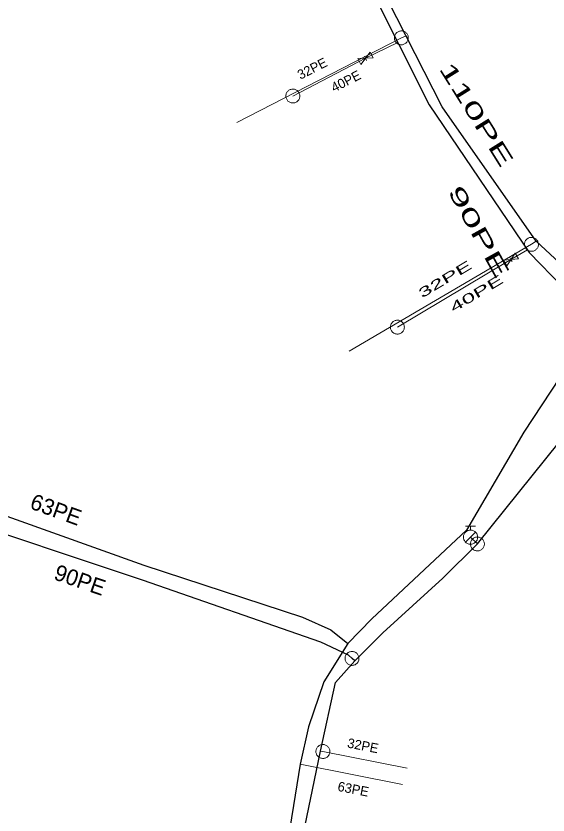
# Model space of a CAD drawing. Extents: x -741806 to -738704, y -1059275 to -1055387.
# Drawn here: x -740322.4 to -740289, y -1057228.9 to -1057178.6 of the extents above; entities that cross this region are included whole.
import ezdxf

# ---------------------------------------------------------------- set-up
doc = ezdxf.new("R2010")
doc.units = 0
doc.header["$LTSCALE"] = 0.4
for name, color, linetype, lineweight in [('2', 7, 'Continuous', 25), ('21', 7, 'Continuous', 13), ('37', 7, 'Continuous', 13), ('46', 7, 'Continuous', 13), ('50', 7, 'Continuous', 13), ('51', 7, 'Continuous', 13), ('52', 7, 'Continuous', 25), ('56', 7, 'Continuous', 13)]:
    doc.layers.add(name, color=color, linetype=linetype, lineweight=lineweight)
for name, color, linetype in [('5', 7, 'Continuous'), ('53', 7, 'Continuous'), ('54', 7, 'Continuous'), ('55', 7, 'Continuous')]:
    doc.layers.add(name, color=color, linetype=linetype)

msp = doc.modelspace()

# ---------------------------------------------------------------- linework, layer by layer
at = {"layer": '2'}
for points in [[(-740262.96, -1057069.909), (-740269.19, -1057072.669), (-740274.949, -1057077.7), (-740275.559, -1057078.32), (-740280.173, -1057082.526), (-740281.937, -1057084.151), (-740283.887, -1057086.098), (-740285.828, -1057088.145), (-740287.55, -1057089.96), (-740294.199, -1057098.5), (-740299.28, -1057106.06), (-740302.629, -1057112.73), (-740305.219, -1057120.72), (-740306.46, -1057125.389), (-740308.809, -1057139.85), (-740308.96, -1057146.77), (-740308.55, -1057154.01), (-740307.079, -1057159.62), (-740305.57, -1057163.75), (-740300.92, -1057174.76), (-740300.27, -1057176.629), (-740296.46, -1057184.19), (-740290.177, -1057193.486), (-740285.949, -1057197.84)], [(-740285.949, -1057197.84), (-740290.513, -1057204.772), (-740294.12, -1057210.94), (-740300.07, -1057216.52), (-740301.579, -1057218.07), (-740303.1, -1057220.48), (-740304.059, -1057223.3), (-740304.57, -1057225.659), (-740305.55, -1057231.639), (-740307.182, -1057240.935), (-740308.309, -1057246.08), (-740308.647, -1057246.469)], [(-740351.149, -1057201.84), (-740350.76, -1057202.01), (-740350.539, -1057202.1), (-740336.309, -1057206.55), (-740331.34, -1057207.659), (-740329.829, -1057207.85), (-740325.609, -1057209.139), (-740314.399, -1057213.149), (-740304.43, -1057216.419), (-740302.66, -1057217.22), (-740301.579, -1057218.07)]]:
    msp.add_lwpolyline(points, dxfattribs=at)
at = {"layer": '21'}
for points in [[(-740297.92, -1057179.867), (-740298.219, -1057179.99), (-740308.548, -1057185.308)], [(-740289.74, -1057192.772), (-740290.039, -1057192.97), (-740301.491, -1057199.698)], [(-740303.309, -1057224.83), (-740303.149, -1057224.86), (-740297.85, -1057225.899)]]:
    msp.add_lwpolyline(points, dxfattribs=at)
at = {"layer": '37'}
for p, q in [((-740300.468, -1057181.27), (-740300.538, -1057181.137)), ((-740300.468, -1057181.27), (-740300.399, -1057181.403)), ((-740291.328, -1057193.929), (-740291.405, -1057193.8)), ((-740291.328, -1057193.929), (-740291.252, -1057194.058))]:
    msp.add_line(p, q, dxfattribs=at)
for points in [[(-740300.758, -1057181.654), (-740300.179, -1057180.886), (-740299.988, -1057181.253), (-740300.949, -1057181.287)], [(-740291.595, -1057194.329), (-740291.061, -1057193.529), (-740290.849, -1057193.885), (-740291.807, -1057193.973)]]:
    msp.add_lwpolyline(points, close=True, dxfattribs=at)
at = {"layer": '46'}
for points in [[(-740304.65, -1057183.446), (-740304.674, -1057183.407), (-740304.701, -1057183.371), (-740304.732, -1057183.336), (-740304.766, -1057183.306), (-740304.803, -1057183.28), (-740304.843, -1057183.257), (-740304.885, -1057183.239), (-740304.929, -1057183.224), (-740304.974, -1057183.216), (-740305.019, -1057183.212), (-740305.065, -1057183.212), (-740305.111, -1057183.217), (-740305.155, -1057183.227), (-740305.199, -1057183.241), (-740305.241, -1057183.26), (-740305.28, -1057183.283), (-740305.317, -1057183.311), (-740305.351, -1057183.341), (-740305.381, -1057183.376), (-740305.408, -1057183.414), (-740305.43, -1057183.454), (-740305.448, -1057183.495), (-740305.462, -1057183.539), (-740305.471, -1057183.584), (-740305.476, -1057183.63), (-740305.474, -1057183.675), (-740305.47, -1057183.72), (-740305.46, -1057183.766), (-740305.445, -1057183.809), (-740305.426, -1057183.851), (-740305.403, -1057183.89), (-740305.376, -1057183.926), (-740305.345, -1057183.961), (-740305.31, -1057183.991), (-740305.274, -1057184.017), (-740305.234, -1057184.04), (-740305.192, -1057184.058), (-740305.147, -1057184.072), (-740305.103, -1057184.081), (-740305.058, -1057184.085), (-740305.012, -1057184.085), (-740304.966, -1057184.08), (-740304.921, -1057184.071), (-740304.878, -1057184.056), (-740304.836, -1057184.037), (-740304.797, -1057184.014), (-740304.76, -1057183.987), (-740304.726, -1057183.956), (-740304.696, -1057183.921), (-740304.669, -1057183.883), (-740304.647, -1057183.843), (-740304.628, -1057183.802), (-740304.615, -1057183.758), (-740304.606, -1057183.713), (-740304.601, -1057183.667), (-740304.602, -1057183.621), (-740304.607, -1057183.577), (-740304.617, -1057183.531), (-740304.632, -1057183.488), (-740304.65, -1057183.447)], [(-740298.092, -1057197.954), (-740298.118, -1057197.917), (-740298.147, -1057197.882), (-740298.18, -1057197.849), (-740298.216, -1057197.821), (-740298.255, -1057197.797), (-740298.296, -1057197.776), (-740298.339, -1057197.761), (-740298.383, -1057197.749), (-740298.428, -1057197.743), (-740298.474, -1057197.741), (-740298.52, -1057197.744), (-740298.566, -1057197.752), (-740298.609, -1057197.765), (-740298.652, -1057197.781), (-740298.692, -1057197.803), (-740298.731, -1057197.828), (-740298.765, -1057197.858), (-740298.798, -1057197.89), (-740298.826, -1057197.926), (-740298.85, -1057197.965), (-740298.87, -1057198.006), (-740298.886, -1057198.048), (-740298.897, -1057198.093), (-740298.904, -1057198.138), (-740298.906, -1057198.185), (-740298.902, -1057198.23), (-740298.895, -1057198.275), (-740298.883, -1057198.32), (-740298.866, -1057198.362), (-740298.844, -1057198.402), (-740298.819, -1057198.44), (-740298.79, -1057198.475), (-740298.757, -1057198.508), (-740298.72, -1057198.536), (-740298.682, -1057198.56), (-740298.641, -1057198.581), (-740298.598, -1057198.596), (-740298.553, -1057198.608), (-740298.509, -1057198.614), (-740298.463, -1057198.616), (-740298.417, -1057198.613), (-740298.371, -1057198.605), (-740298.328, -1057198.593), (-740298.285, -1057198.576), (-740298.245, -1057198.554), (-740298.206, -1057198.529), (-740298.171, -1057198.5), (-740298.139, -1057198.467), (-740298.111, -1057198.431), (-740298.087, -1057198.392), (-740298.067, -1057198.351), (-740298.05, -1057198.308), (-740298.04, -1057198.264), (-740298.033, -1057198.219), (-740298.031, -1057198.172), (-740298.034, -1057198.126), (-740298.042, -1057198.082), (-740298.054, -1057198.037), (-740298.071, -1057197.995), (-740298.092, -1057197.955)]]:
    msp.add_lwpolyline(points, dxfattribs=at)
at = {"layer": '50'}
for p, q in [((-740294.178, -1057210.685), (-740293.87, -1057210.685)), ((-740293.87, -1057210.936), (-740293.87, -1057210.685)), ((-740293.563, -1057210.685), (-740293.87, -1057210.685)), ((-740293.87, -1057211.383), (-740294.187, -1057211.7)), ((-740293.87, -1057211.383), (-740293.554, -1057211.071))]:
    msp.add_line(p, q, dxfattribs=at)
msp.add_lwpolyline([(-740293.426, -1057211.387), (-740293.428, -1057211.338), (-740293.433, -1057211.292), (-740293.446, -1057211.246), (-740293.463, -1057211.203), (-740293.482, -1057211.163), (-740293.509, -1057211.122), (-740293.538, -1057211.087), (-740293.571, -1057211.052), (-740293.606, -1057211.022), (-740293.646, -1057210.998), (-740293.687, -1057210.976), (-740293.73, -1057210.957), (-740293.776, -1057210.947), (-740293.822, -1057210.939), (-740293.868, -1057210.936), (-740293.914, -1057210.939), (-740293.959, -1057210.944), (-740294.005, -1057210.957), (-740294.049, -1057210.974), (-740294.092, -1057210.995), (-740294.13, -1057211.02), (-740294.167, -1057211.049), (-740294.2, -1057211.082), (-740294.229, -1057211.117), (-740294.256, -1057211.157), (-740294.278, -1057211.198), (-740294.294, -1057211.241), (-740294.308, -1057211.287), (-740294.313, -1057211.333), (-740294.32, -1057211.379), (-740294.317, -1057211.427), (-740294.309, -1057211.473), (-740294.298, -1057211.516), (-740294.282, -1057211.562), (-740294.26, -1057211.603), (-740294.236, -1057211.643), (-740294.206, -1057211.678), (-740294.174, -1057211.713), (-740294.136, -1057211.743), (-740294.098, -1057211.767), (-740294.055, -1057211.789), (-740294.012, -1057211.805), (-740293.969, -1057211.819), (-740293.92, -1057211.827), (-740293.874, -1057211.83), (-740293.828, -1057211.827), (-740293.782, -1057211.819), (-740293.736, -1057211.808), (-740293.693, -1057211.792), (-740293.65, -1057211.77), (-740293.612, -1057211.746), (-740293.574, -1057211.716), (-740293.542, -1057211.684), (-740293.512, -1057211.649), (-740293.488, -1057211.608), (-740293.464, -1057211.568), (-740293.447, -1057211.524), (-740293.437, -1057211.479), (-740293.429, -1057211.433)], close=True, dxfattribs=at)
at = {"layer": '51'}
for points in [[(-740298.623, -1057180.155), (-740298.604, -1057180.195), (-740298.581, -1057180.234), (-740298.553, -1057180.272), (-740298.522, -1057180.304), (-740298.487, -1057180.334), (-740298.449, -1057180.361), (-740298.409, -1057180.382), (-740298.367, -1057180.401), (-740298.323, -1057180.413), (-740298.278, -1057180.422), (-740298.232, -1057180.426), (-740298.186, -1057180.425), (-740298.141, -1057180.42), (-740298.097, -1057180.409), (-740298.053, -1057180.393), (-740298.011, -1057180.374), (-740297.972, -1057180.351), (-740297.936, -1057180.323), (-740297.903, -1057180.291), (-740297.873, -1057180.256), (-740297.847, -1057180.218), (-740297.824, -1057180.179), (-740297.807, -1057180.136), (-740297.794, -1057180.093), (-740297.785, -1057180.047), (-740297.781, -1057180.001), (-740297.783, -1057179.956), (-740297.788, -1057179.91), (-740297.799, -1057179.866), (-740297.814, -1057179.822), (-740297.834, -1057179.782), (-740297.857, -1057179.743), (-740297.885, -1057179.706), (-740297.916, -1057179.673), (-740297.951, -1057179.643), (-740297.989, -1057179.616), (-740298.029, -1057179.595), (-740298.071, -1057179.576), (-740298.115, -1057179.564), (-740298.16, -1057179.555), (-740298.205, -1057179.551), (-740298.252, -1057179.552), (-740298.297, -1057179.558), (-740298.341, -1057179.568), (-740298.385, -1057179.584), (-740298.426, -1057179.603), (-740298.465, -1057179.627), (-740298.502, -1057179.654), (-740298.535, -1057179.686), (-740298.565, -1057179.721), (-740298.591, -1057179.759), (-740298.613, -1057179.798), (-740298.63, -1057179.841), (-740298.644, -1057179.884), (-740298.652, -1057179.93), (-740298.656, -1057179.976), (-740298.655, -1057180.021), (-740298.649, -1057180.067), (-740298.639, -1057180.111), (-740298.624, -1057180.154)], [(-740290.403, -1057193.21), (-740290.377, -1057193.246), (-740290.346, -1057193.28), (-740290.312, -1057193.311), (-740290.275, -1057193.337), (-740290.235, -1057193.36), (-740290.193, -1057193.379), (-740290.149, -1057193.392), (-740290.104, -1057193.402), (-740290.059, -1057193.405), (-740290.013, -1057193.405), (-740289.968, -1057193.4), (-740289.922, -1057193.391), (-740289.879, -1057193.376), (-740289.838, -1057193.357), (-740289.798, -1057193.334), (-740289.761, -1057193.307), (-740289.727, -1057193.276), (-740289.697, -1057193.242), (-740289.67, -1057193.204), (-740289.648, -1057193.164), (-740289.63, -1057193.122), (-740289.615, -1057193.079), (-740289.607, -1057193.034), (-740289.602, -1057192.989), (-740289.602, -1057192.942), (-740289.607, -1057192.896), (-740289.617, -1057192.853), (-740289.632, -1057192.808), (-740289.651, -1057192.767), (-740289.674, -1057192.727), (-740289.701, -1057192.691), (-740289.732, -1057192.657), (-740289.767, -1057192.626), (-740289.803, -1057192.6), (-740289.843, -1057192.578), (-740289.885, -1057192.559), (-740289.929, -1057192.546), (-740289.974, -1057192.536), (-740290.019, -1057192.532), (-740290.065, -1057192.532), (-740290.111, -1057192.537), (-740290.156, -1057192.547), (-740290.199, -1057192.562), (-740290.241, -1057192.58), (-740290.28, -1057192.604), (-740290.317, -1057192.631), (-740290.351, -1057192.662), (-740290.381, -1057192.695), (-740290.408, -1057192.733), (-740290.43, -1057192.773), (-740290.448, -1057192.815), (-740290.463, -1057192.858), (-740290.471, -1057192.904), (-740290.476, -1057192.949), (-740290.476, -1057192.995), (-740290.471, -1057193.041), (-740290.461, -1057193.085), (-740290.446, -1057193.129), (-740290.427, -1057193.17), (-740290.404, -1057193.209)], [(-740293.128, -1057211.503), (-740293.161, -1057211.472), (-740293.198, -1057211.445), (-740293.238, -1057211.422), (-740293.279, -1057211.403), (-740293.322, -1057211.389), (-740293.368, -1057211.378), (-740293.413, -1057211.374), (-740293.459, -1057211.373), (-740293.504, -1057211.378), (-740293.549, -1057211.387), (-740293.593, -1057211.401), (-740293.635, -1057211.419), (-740293.675, -1057211.441), (-740293.712, -1057211.468), (-740293.746, -1057211.499), (-740293.777, -1057211.532), (-740293.804, -1057211.569), (-740293.827, -1057211.608), (-740293.846, -1057211.651), (-740293.861, -1057211.695), (-740293.87, -1057211.739), (-740293.876, -1057211.784), (-740293.876, -1057211.83), (-740293.872, -1057211.875), (-740293.862, -1057211.921), (-740293.848, -1057211.965), (-740293.83, -1057212.006), (-740293.807, -1057212.046), (-740293.78, -1057212.083), (-740293.75, -1057212.118), (-740293.717, -1057212.148), (-740293.68, -1057212.175), (-740293.64, -1057212.199), (-740293.599, -1057212.217), (-740293.555, -1057212.232), (-740293.51, -1057212.242), (-740293.465, -1057212.247), (-740293.419, -1057212.248), (-740293.374, -1057212.242), (-740293.329, -1057212.233), (-740293.285, -1057212.22), (-740293.242, -1057212.202), (-740293.203, -1057212.178), (-740293.166, -1057212.153), (-740293.132, -1057212.122), (-740293.1, -1057212.088), (-740293.074, -1057212.051), (-740293.05, -1057212.012), (-740293.032, -1057211.97), (-740293.017, -1057211.926), (-740293.008, -1057211.881), (-740293.002, -1057211.836), (-740293.002, -1057211.79), (-740293.006, -1057211.745), (-740293.016, -1057211.7), (-740293.029, -1057211.656), (-740293.047, -1057211.615), (-740293.071, -1057211.574), (-740293.097, -1057211.537), (-740293.127, -1057211.504)], [(-740301.655, -1057218.729), (-740301.682, -1057218.765), (-740301.706, -1057218.804), (-740301.725, -1057218.847), (-740301.74, -1057218.889), (-740301.75, -1057218.934), (-740301.756, -1057218.98), (-740301.756, -1057219.025), (-740301.752, -1057219.071), (-740301.743, -1057219.116), (-740301.729, -1057219.159), (-740301.711, -1057219.202), (-740301.689, -1057219.242), (-740301.663, -1057219.28), (-740301.633, -1057219.314), (-740301.599, -1057219.345), (-740301.562, -1057219.373), (-740301.523, -1057219.396), (-740301.482, -1057219.415), (-740301.438, -1057219.43), (-740301.393, -1057219.44), (-740301.348, -1057219.445), (-740301.302, -1057219.446), (-740301.256, -1057219.441), (-740301.212, -1057219.433), (-740301.168, -1057219.419), (-740301.125, -1057219.401), (-740301.086, -1057219.379), (-740301.048, -1057219.352), (-740301.014, -1057219.322), (-740300.982, -1057219.289), (-740300.956, -1057219.252), (-740300.932, -1057219.213), (-740300.913, -1057219.171), (-740300.898, -1057219.128), (-740300.888, -1057219.084), (-740300.882, -1057219.038), (-740300.882, -1057218.992), (-740300.885, -1057218.946), (-740300.895, -1057218.902), (-740300.908, -1057218.858), (-740300.926, -1057218.816), (-740300.949, -1057218.775), (-740300.975, -1057218.739), (-740301.005, -1057218.704), (-740301.039, -1057218.673), (-740301.075, -1057218.645), (-740301.115, -1057218.622), (-740301.156, -1057218.602), (-740301.2, -1057218.588), (-740301.245, -1057218.578), (-740301.29, -1057218.573), (-740301.336, -1057218.571), (-740301.381, -1057218.576), (-740301.426, -1057218.584), (-740301.47, -1057218.598), (-740301.513, -1057218.616), (-740301.552, -1057218.638), (-740301.59, -1057218.665), (-740301.624, -1057218.695), (-740301.654, -1057218.729)], [(-740302.719, -1057224.941), (-740302.713, -1057224.896), (-740302.711, -1057224.85), (-740302.715, -1057224.804), (-740302.723, -1057224.76), (-740302.736, -1057224.716), (-740302.753, -1057224.673), (-740302.775, -1057224.633), (-740302.801, -1057224.595), (-740302.831, -1057224.56), (-740302.864, -1057224.529), (-740302.9, -1057224.501), (-740302.939, -1057224.476), (-740302.98, -1057224.456), (-740303.023, -1057224.441), (-740303.068, -1057224.43), (-740303.114, -1057224.424), (-740303.159, -1057224.423), (-740303.205, -1057224.426), (-740303.25, -1057224.435), (-740303.294, -1057224.448), (-740303.336, -1057224.466), (-740303.377, -1057224.487), (-740303.414, -1057224.513), (-740303.449, -1057224.542), (-740303.481, -1057224.576), (-740303.509, -1057224.612), (-740303.533, -1057224.651), (-740303.553, -1057224.693), (-740303.568, -1057224.736), (-740303.579, -1057224.78), (-740303.585, -1057224.825), (-740303.586, -1057224.871), (-740303.583, -1057224.917), (-740303.575, -1057224.961), (-740303.561, -1057225.005), (-740303.544, -1057225.048), (-740303.522, -1057225.088), (-740303.497, -1057225.126), (-740303.466, -1057225.161), (-740303.434, -1057225.192), (-740303.397, -1057225.22), (-740303.358, -1057225.245), (-740303.317, -1057225.264), (-740303.274, -1057225.28), (-740303.229, -1057225.29), (-740303.184, -1057225.297), (-740303.138, -1057225.297), (-740303.093, -1057225.295), (-740303.047, -1057225.286), (-740303.003, -1057225.273), (-740302.961, -1057225.255), (-740302.921, -1057225.234), (-740302.883, -1057225.208), (-740302.848, -1057225.179), (-740302.816, -1057225.145), (-740302.788, -1057225.109), (-740302.765, -1057225.07), (-740302.745, -1057225.028), (-740302.73, -1057224.985), (-740302.719, -1057224.942)]]:
    msp.add_lwpolyline(points, dxfattribs=at)
at = {"layer": '52'}
msp.add_line((-740293.44, -1057211.81), (-740293.87, -1057211.379), dxfattribs=at)
for points in [[(-740283.129, -1057198.97), (-740283.26, -1057198.81), (-740289.74, -1057192.772), (-740295.66, -1057184.32), (-740299.64, -1057176.48), (-740305.079, -1057163.11), (-740306.469, -1057159.919), (-740308.03, -1057153.929), (-740308.37, -1057146.06), (-740307.77, -1057139.98), (-740305.71, -1057125.55), (-740304.82, -1057121.77), (-740302.16, -1057112.889), (-740299.12, -1057106.889), (-740298.43, -1057105.73), (-740293.78, -1057098.919), (-740287, -1057090.56), (-740282.309, -1057085.5), (-740278.449, -1057081.76), (-740275.899, -1057079.48), (-740275.289, -1057078.97), (-740268.949, -1057073.48), (-740263.329, -1057070.639), (-740262.78, -1057070.48)], [(-740317.443, -1057290.145), (-740317.35, -1057289.69), (-740316.219, -1057284.629), (-740312.52, -1057267.659), (-740311.399, -1057262.36), (-740306.51, -1057241.179), (-740304.539, -1057230.81), (-740303.309, -1057224.83), (-740302.359, -1057220.52), (-740301.14, -1057219.159), (-740299.39, -1057217.389), (-740295.62, -1057213.96), (-740293.44, -1057211.81), (-740283.129, -1057198.97)], [(-740301.14, -1057219.159), (-740301.32, -1057219.01), (-740301.539, -1057218.81), (-740303.28, -1057217.99), (-740314.489, -1057214.08), (-740327.18, -1057209.85), (-740330.829, -1057208.86), (-740336.92, -1057207.07), (-740350.059, -1057202.919), (-740350.629, -1057202.74), (-740351.27, -1057202.44)]]:
    msp.add_lwpolyline(points, dxfattribs=at)
at = {"layer": '56'}
msp.add_line((-740298.149, -1057226.94), (-740304.57, -1057225.659), dxfattribs=at)
for points in [[(-740305.039, -1057183.649), (-740300.469, -1057181.27), (-740298.43, -1057180.28)], [(-740298.469, -1057198.179), (-740291.329, -1057193.929), (-740290.295, -1057193.311)]]:
    msp.add_lwpolyline(points, dxfattribs=at)

# ---------------------------------------------------------------- texts
at = {"layer": '5', "width": 1.95}
msp.add_text('90PE', height=1, rotation=299, dxfattribs=at).set_placement((-740295.332, -1057189.627))
at = {"layer": '5'}
msp.add_text('63PE', height=1, rotation=340, dxfattribs=at).set_placement((-740321.63, -1057209.562))
at = {"layer": '53', "width": 1.85}
msp.add_text('110PE ', height=1, rotation=302, dxfattribs=at).set_placement((-740295.887, -1057181.917))
at = {"layer": '53'}
msp.add_text('90PE', height=1, rotation=341, dxfattribs=at).set_placement((-740320.122, -1057214.02))
at = {"layer": '54'}
for rotation, p in [(27, (-740304.56, -1057182.627)), (349, (-740301.652, -1057224.601))]:
    msp.add_text('32PE', height=0.6, rotation=rotation, dxfattribs=at).set_placement(p)
at = {"layer": '54', "width": 1.9}
msp.add_text('32PE', height=0.6, rotation=31, dxfattribs=at).set_placement((-740296.923, -1057196.377))
at = {"layer": '55'}
for s, rotation, p in [('40PE', 27, (-740302.44, -1057183.427)), ('63PE', 349, (-740302.26, -1057227.328))]:
    msp.add_text(s, height=0.6, rotation=rotation, dxfattribs=at).set_placement(p)
at = {"layer": '55', "width": 1.9}
msp.add_text('40PE', height=0.6, rotation=31, dxfattribs=at).set_placement((-740294.942, -1057197.274))

doc.saveas('drawing.dxf')
